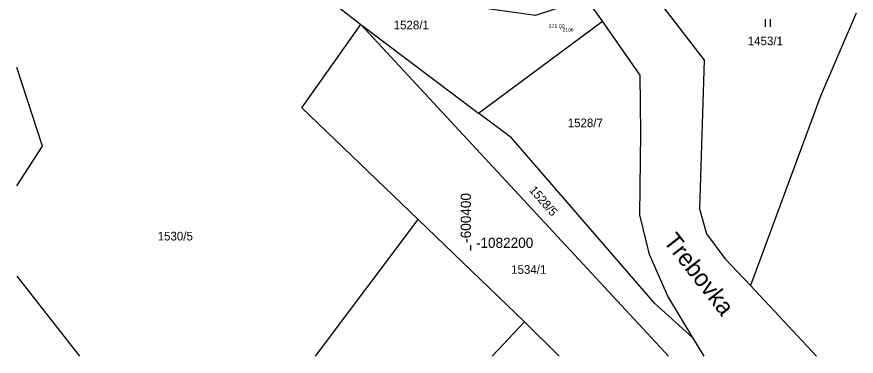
# Model space of a CAD drawing. Extents: x -600490 to -600324, y -1082221 to -1082039.
# Drawn here: x -600489.5 to -600324, y -1082221.4 to -1082154.4 of the extents above; entities that cross this region are included whole.
import ezdxf

# ---------------------------------------------------------------- set-up
doc = ezdxf.new("R2010")
doc.units = 0
for name, color, linetype in [('1-Body', 7, 'Continuous'), ('2-Čísla-bodů', 7, 'Continuous'), ('20-Bod-výškopisu', 7, 'Continuous'), ('3-Výšky-bodů', 7, 'Continuous'), ('63-Měřická-síť', 7, 'Continuous'), ('Level 48', 7, 'Continuous')]:
    doc.layers.add(name, color=color, linetype=linetype)

msp = doc.modelspace()

# ---------------------------------------------------------------- linework, layer by layer
at = {"layer": '1-Body'}
msp.add_line((-600382.19, -1082156.63), (-600382.19, -1082156.63), dxfattribs=at)
at = {"layer": 'Level 48'}
for p, q in [((-600437.82, -1082143.15), (-600421.71, -1082155.91)), ((-600398.5, -1082173.39), (-600374.07, -1082155.26)), ((-600341.931, -1082156.4), (-600341.931, -1082154.9)), ((-600340.93, -1082156.4), (-600340.93, -1082154.9)), ((-600324.04, -1082153.7), (-600331.06, -1082170.06)), ((-600421.71, -1082155.91), (-600398.5, -1082173.39)), ((-600421.71, -1082155.91), (-600361.024, -1082221.379)), ((-600331.06, -1082170.06), (-600344.89, -1082207.45)), ((-600392, -1082178.29), (-600398.5, -1082173.39)), ((-600430.641, -1082221.379), (-600410.4, -1082194.38)), ((-600389.46, -1082214.57), (-600410.4, -1082194.38)), ((-600489.514, -1082205.564), (-600477.122, -1082221.379)), ((-600344.89, -1082207.45), (-600331.836, -1082221.379)), ((-600356.16, -1082217.83), (-600361.18, -1082209.5)), ((-600389.46, -1082214.57), (-600395.809, -1082221.379)), ((-600382.626, -1082221.379), (-600389.46, -1082214.57)), ((-600354.022, -1082221.379), (-600356.16, -1082217.83))]:
    msp.add_line(p, q, dxfattribs=at)
for points in [[(-600374.07, -1082155.26), (-600377.2, -1082150.79), (-600387.25, -1082154.15), (-600408.42, -1082151.19), (-600423.2, -1082132.6)], [(-600365.05, -1082148.57), (-600354.03, -1082162.96), (-600354.93, -1082192.29), (-600353.55, -1082197.21), (-600349.92, -1082202.09), (-600344.89, -1082207.45)], [(-600361.18, -1082209.5), (-600364.82, -1082201.29), (-600366.67, -1082193.46), (-600366.47, -1082177.33), (-600366.62, -1082165.9), (-600374.07, -1082155.26)], [(-600410.4, -1082194.38), (-600433.3, -1082172.37), (-600421.71, -1082155.91)], [(-600489.514, -1082187.758), (-600484.44, -1082179.95), (-600489.514, -1082164.437)], [(-600356.16, -1082217.83), (-600363.71, -1082210.97), (-600392, -1082178.29)], [(-600400, -1082200.55), (-600400, -1082200), (-600400, -1082199.45)]]:
    msp.add_lwpolyline(points, dxfattribs=at)

# ---------------------------------------------------------------- texts
at = {"layer": '2-Čísla-bodů'}
msp.add_text(' 2106', height=0.7, dxfattribs=at).set_placement((-600382.19, -1082157.33))
at = {"layer": '20-Bod-výškopisu'}
msp.add_text('.', height=0.1, dxfattribs=at).set_placement((-600382.19, -1082156.63))
msp.add_text('.', height=0.1, dxfattribs=at).set_placement((-600382.19, -1082156.63))
at = {"layer": '3-Výšky-bodů'}
msp.add_text('371 00 ', height=0.75, dxfattribs=at).set_placement((-600384.69, -1082156.63))
at = {"layer": '63-Měřická-síť'}
msp.add_text('T', height=0.3, dxfattribs=at).set_placement((-600382.39, -1082156.93))
msp.add_text('T', height=0.3, dxfattribs=at).set_placement((-600382.39, -1082156.93))
at = {"layer": 'Level 48'}
for s, height, p in [('1528/1', 1.7, (-600415.226, -1082156.875)), ('1453/1', 1.7, (-600345.426, -1082160.015)), ('1528/7', 1.7, (-600380.916, -1082176.185)), ('1530/5', 1.7, (-600461.75, -1082198.535)), ('-1082200', 2, (-600399, -1082200)), ('1534/1', 1.7, (-600392.076, -1082205.115))]:
    msp.add_text(s, height=height, dxfattribs=at).set_placement(p)
for s, height, rotation, p in [('1528/5', 1.7, 311, (-600388.61, -1082188.668)), ('-600400', 2, 90, (-600400, -1082199)), ('Trebovka', 3.4, 308, (-600362.171, -1082198.729))]:
    msp.add_text(s, height=height, rotation=rotation, dxfattribs=at).set_placement(p)

doc.saveas('drawing.dxf')
